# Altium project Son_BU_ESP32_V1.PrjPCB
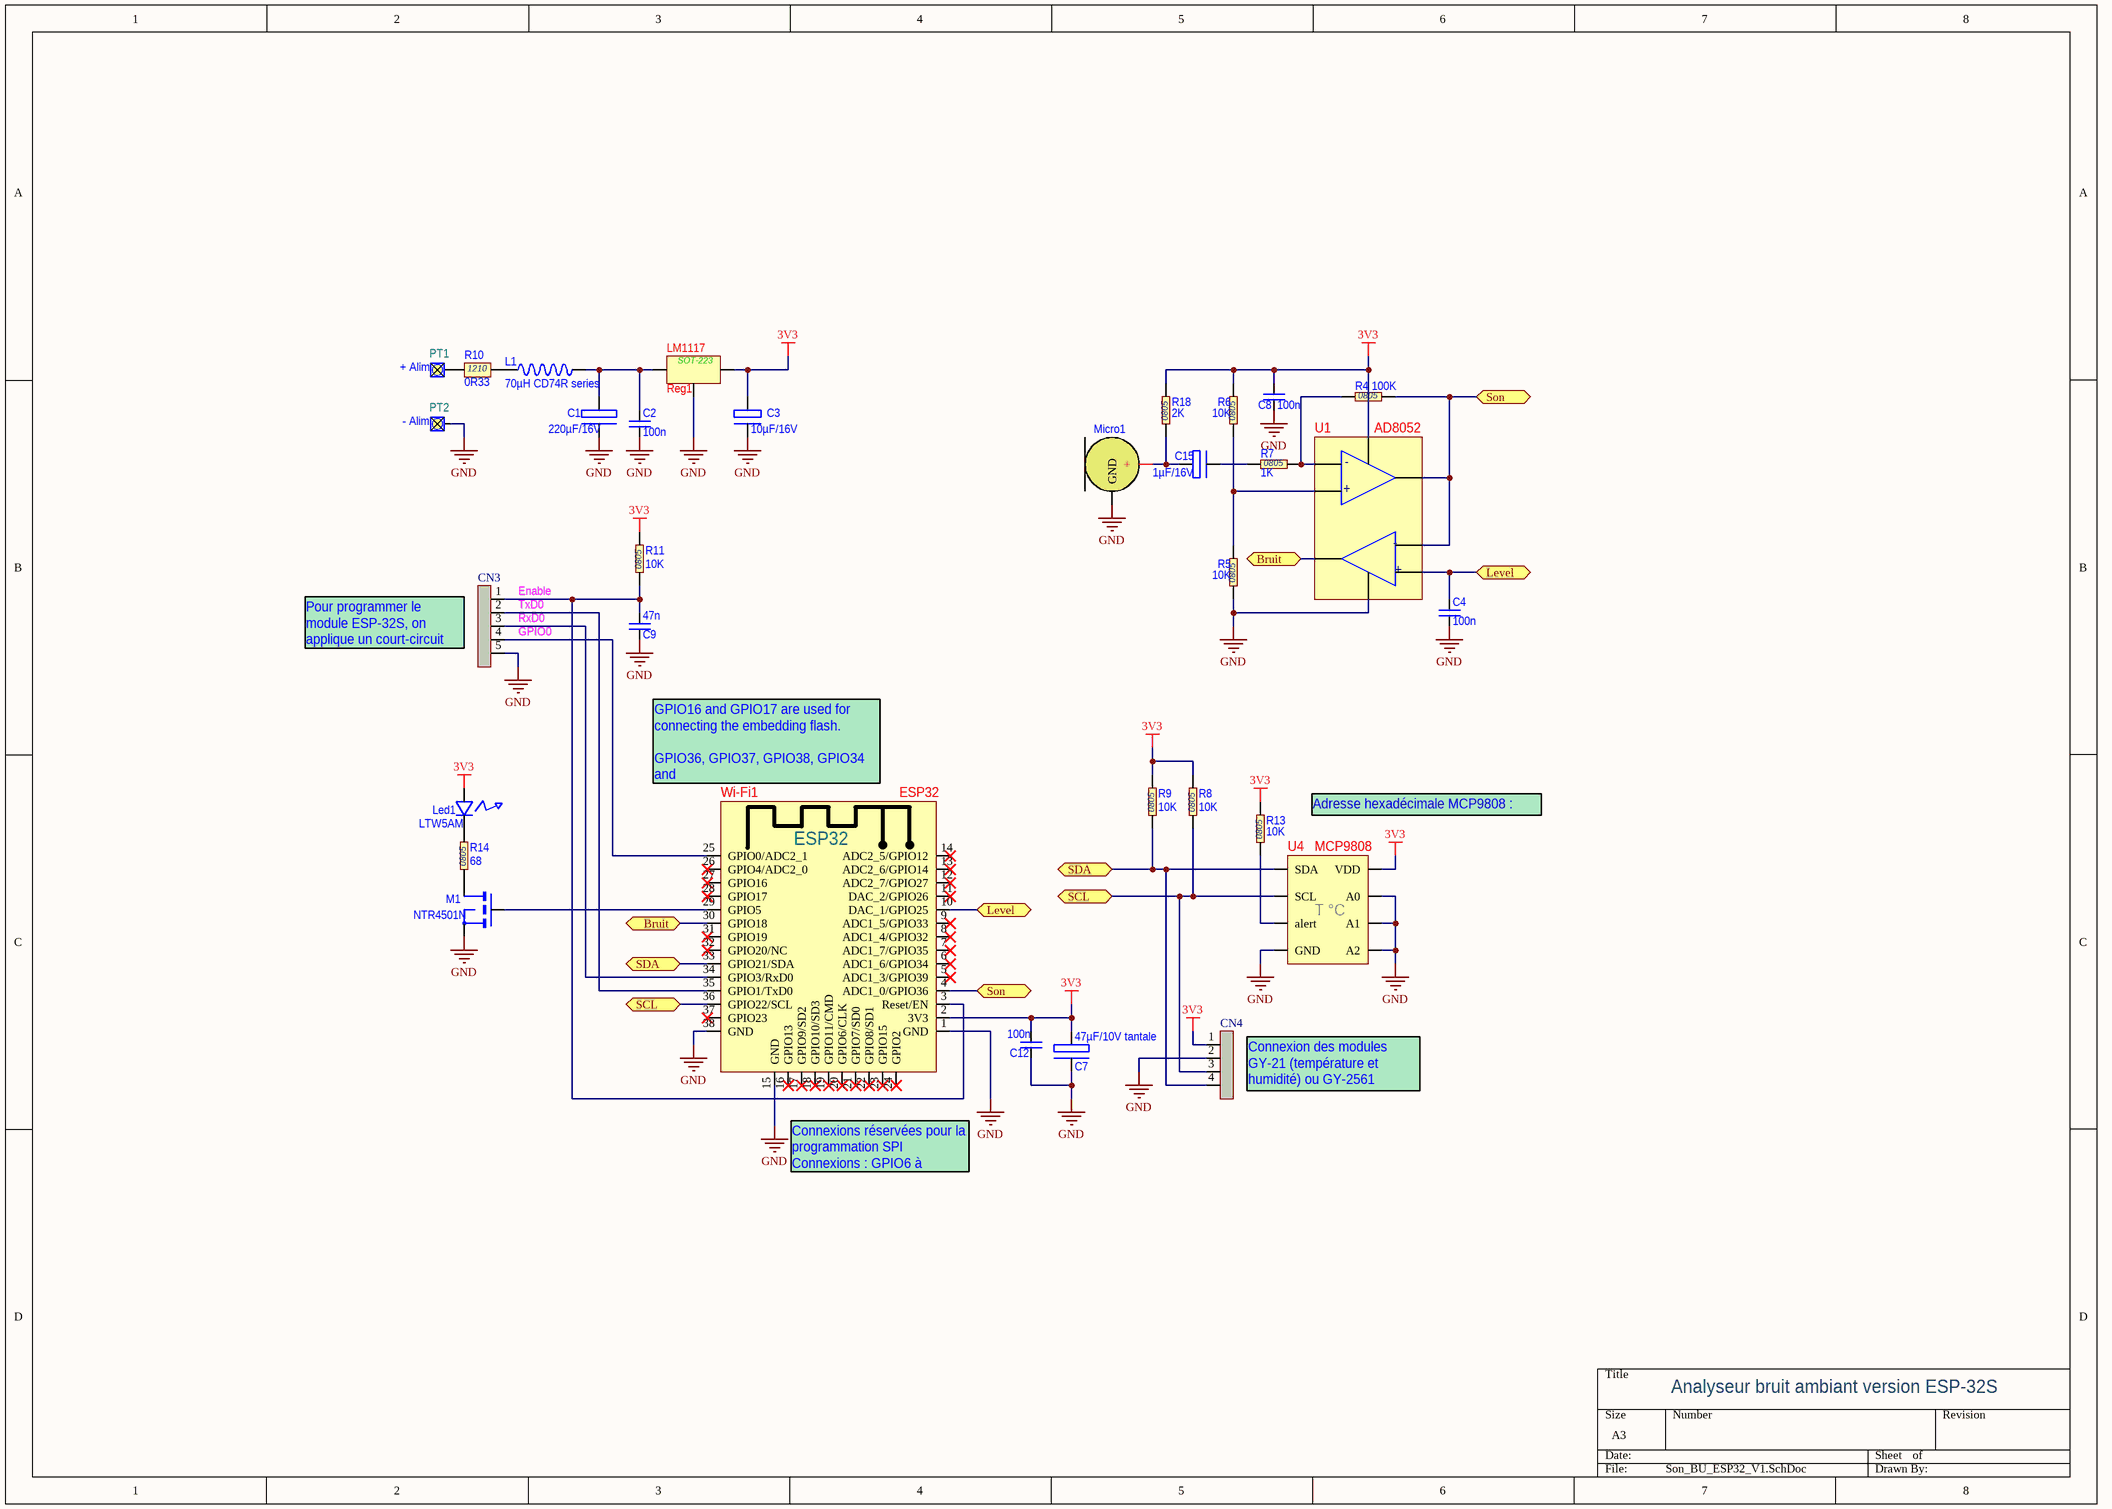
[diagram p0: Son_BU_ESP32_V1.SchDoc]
1 sheet, 32 parts. Net scope: flat (ports and power ports of the same name join across sheets).
Board file: Son_BU_ESP32_V1.PcbDoc

## Sheet Son_BU_ESP32_V1.SchDoc
size A3

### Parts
C1  220µF/16V  [7343-31]
C2  100n  [0805]
C3  10µF/16V  [Tantale 10µF/16V]
C4  100n  [0805]
C7  47µF/10V tantale  [tantale 47µF/10V]
C8  100n  [0805]
C9  47n  [0805]
C12  100n  [0805]
C15  1µF/16V  [3216-18]
CN3  inch_ligne 1x5  [INCH_1x5_droit]  (value not drawn)
CN4  inch_ligne 1x4  [INCH_1x4_droit]  (value not drawn)
L1  70µH CD74R series  [SELF CD74R]
Led1  LTW5AM  [LTW5AM]
M1  NTR4501N  [SOT23 (NTR4501)]
Micro1  Electret  [Micro_electret simple]  (value not drawn)
PT1  + Alim  [Pointe de test]
PT2  - Alim  [Pointe de test]
R4  100K  [0805]
R5  10K  [0805]
R6  10K  [0805]
R7  1K  [0805]
R8  10K  [0805]
R9  10K  [0805]
R10  0R33  [1210]
R11  10K  [0805]
R13  10K  [0805]
R14  68  [0805]
R18  2K  [0805]
Reg1  LM1117  [SOT223]
U1  AD8052  [SOIC08]
U4  MCP9808  [MSOP-08]
Wi-Fi1  ESP32  [ESP32]

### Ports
Bruit, Level, SCL, SDA, Son

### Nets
3V3: C3.1(V+) C7.1(V+) C8.2(CT2) C12.2(CT2) CN4.1 Led1.1(anode) R6.2(CT2) R8.2(CT2) R9.2(CT2) R11.2(CT2) R13.2(CT2) R18.2(CT2) Reg1.2(OUT) U1.8(V+) U4.8(VDD) Wi-Fi1.2(3V3)
GND: C1.2(V-) C2.1(CT1) C3.2(V-) C4.1(CT1) C7.2(V-) C8.1(CT1) C9.1(CT1) C12.1(CT1) CN3.5 CN4.2 M1.3(S) Micro1.0(GND) PT2.1(PIN) R5.1(CT1) Reg1.1(GND) U1.4(V-) U4.4(GND) U4.5(A2) U4.6(A1) U4.7(A0) Wi-Fi1.1(GND) Wi-Fi1.15(GND) Wi-Fi1.38(GND)
Enable: C9.2(CT2) CN3.1 R11.1(CT1) Wi-Fi1.3(Reset/EN)
GPIO0: CN3.4 Wi-Fi1.25(GPIO0/ADC2_1)
RxD0: CN3.3 Wi-Fi1.34(GPIO3/RxD0)
TxD0: CN3.2 Wi-Fi1.35(GPIO1/TxD0)
NetC1_1: C1.1(V+) C2.2(CT2) L1.1(CT1) Reg1.3(IN)
NetC4_2: C4.2(CT2) U1.5(in+) Wi-Fi1.10(DAC_1/GPIO25) ; port Level
NetC15_1: C15.1(V+) Micro1.1(+) R18.1(CT1)
NetC15_2: C15.2(V-) R7.1(CT1)
NetCN4_3: CN4.3 R8.1(CT1) U4.2(SCL) Wi-Fi1.36(GPIO22/SCL) ; port SCL
NetCN4_4: CN4.4 R9.1(CT1) U4.1(SDA) Wi-Fi1.33(GPIO21/SDA) ; port SDA
NetL1_2: L1.2(CT2) R10.2(CT2)
NetLed1_2: Led1.2(cathode) R14.2(CT2)
NetM1_1: M1.1(D) R14.1(CT1)
NetM1_2: M1.2(G) Wi-Fi1.29(GPIO5)
NetPT1_1: PT1.1(PIN) R10.1(CT1)
NetR4_1: R4.1(CT1) R7.2(CT2) U1.2(in-)
NetR4_2: R4.2(CT2) U1.1(out) U1.6(in-) Wi-Fi1.4(ADC1_0/GPIO36) ; port Son
NetR5_2: R5.2(CT2) R6.1(CT1) U1.3(in+)
NetR13_1: R13.1(CT1) U4.3(alert)
NetU1_7: U1.7(out) Wi-Fi1.30(GPIO18) ; port Bruit

Not connected (* = marked no-connect by the designer): Wi-Fi1 5(ADC1_3/GPIO39)* 6(ADC1_6/GPIO34)* 7(ADC1_7/GPIO35)* 8(ADC1_4/GPIO32)* 9(ADC1_5/GPIO33)* 11(DAC_2/GPIO26)* 12(ADC2_7/GPIO27)* 13(ADC2_6/GPIO14)* 14(ADC2_5/GPIO12)* 16(GPIO13)* 17(GPIO9/SD2)* 18(GPIO10/SD3)* 19(GPIO11/CMD)* 20(GPIO6/CLK)* 21(GPIO7/SD0)* 22(GPIO8/SD1)* 23(GPIO15)* 24(GPIO2)* 26(GPIO4/ADC2_0)* 27(GPIO16)* 28(GPIO17)* 31(GPIO19)* 32(GPIO20/NC)* 37(GPIO23)*

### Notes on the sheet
- (near CN3) Pour programmer le module ESP-32S, on applique un court-circuit entre 4 et 5.
- GPIO16 and GPIO17 are used for
  connecting the embedding flash.
  GPIO36, GPIO37, GPIO38, GPIO34 and
  GPIO35 can only be used for input.
- Adresse hexadécimale MCP9808 : 0x3_
- (near CN4) Connexion des modules GY-21 (température et humidité) ou GY-2561 (Luxmètre)
- (near Wi-Fi1) Connexions réservées pour la programmation SPI
  Connexions : GPIO6 à GPIO11
- Analyseur bruit ambiant version ESP-32S

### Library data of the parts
C1 = tantale 220µF/16V: 253-5290 case 7343-31
C2 C4 C8 C9 C12 = Cap_CMS_0805: CMS 0805
C3 = tantale 10µF/16V: 145-7461 case 3216-18
C7 = tantale 47µF/10V: 175-4168
C15 = tantale 1µF/16V: 145-7406 case 3216-18
CN3 = Inch_1x5_droit
CN4 = Inch_1x4_droit
L1 = Self CD74R: SMT CD74R Aliexpress
Led1 = LTW5AM LED: LED Golden Dragon Plus
M1 = NTR4501N: MOSFET canal N
Micro1 = Microphone_03: Microphone électret
PT1 PT2 = PTEST: pointe de test CI 133-6225
R4-R9 R11 R13 R14 R18 = Res CMS 0805: CMS 0805
R10 = Res CMS 1210 ERJ14B: CMS 1210
Reg1 = LM1117/800mA: Régulateur SOT-223
U1 = AD8052: AOP
U4 = MCP9808: Digital temperature Sensor
Wi-Fi1 = ESP32: ESP32 module µC Bluetooth Wi-Fi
